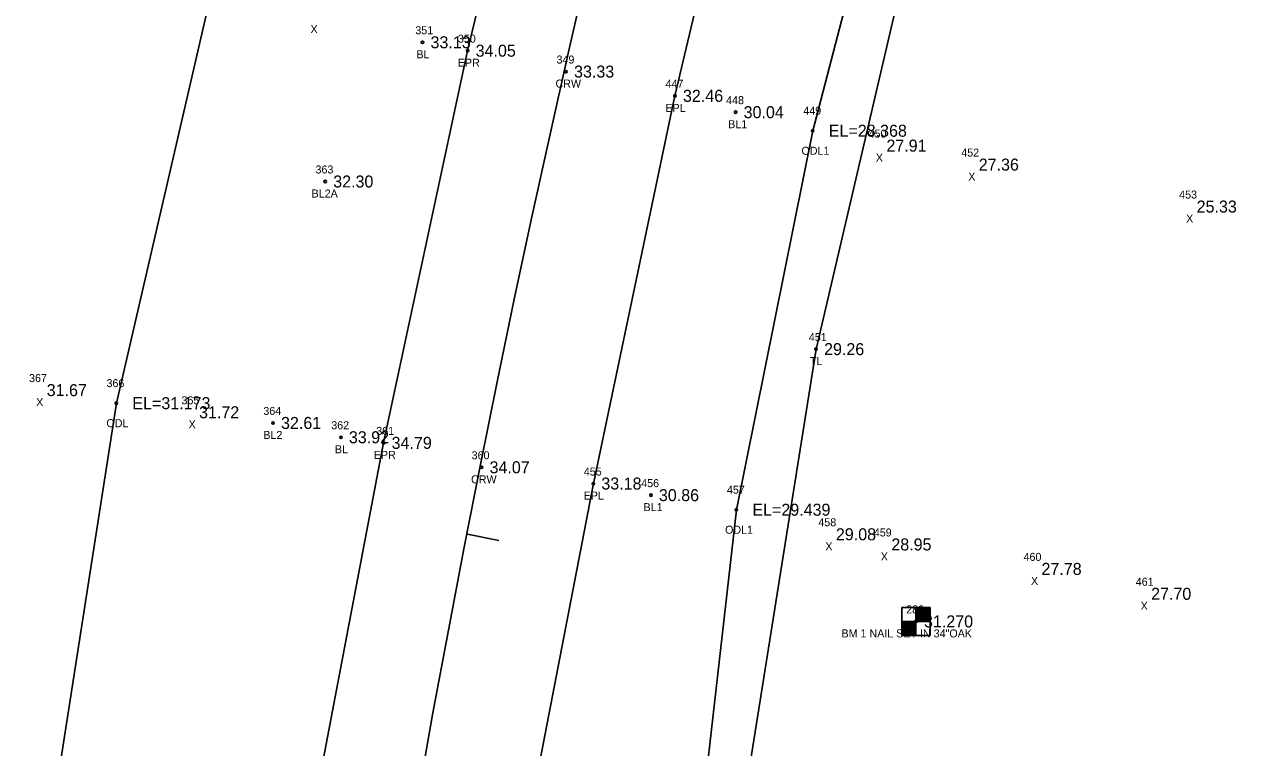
# Model space of a CAD drawing. Extents: x 2042117 to 2045853, y 303080 to 309569.
# Drawn here: x 2042820 to 2042971.5, y 307687.9 to 307778.3 of the extents above; entities that cross this region are included whole.
import ezdxf

# ---------------------------------------------------------------- set-up
doc = ezdxf.new("R2010")
doc.units = 0
for name, color, linetype in [('RD_DTM_BkLn_txCode', 7, 'Continuous'), ('RD_EX_H2O', 7, 'Continuous'), ('RD_EX_H2O_txCode', 7, 'Continuous'), ('RD_EX_Misc_txCode', 7, 'Continuous'), ('RD_EX_Road', 7, 'Continuous'), ('RD_EX_Road_txCode', 7, 'Continuous'), ('RD_EX_TX_H2O_ELEV', 7, 'Continuous'), ('RD_EX_TX_Misc_ELEV', 7, 'Continuous'), ('RD_EX_TX_Road_ELEV', 7, 'Continuous'), ('RD_EX_TX_VEG_ELEV', 7, 'Continuous'), ('RD_EX_VEG', 7, 'Continuous'), ('RD_EX_VEG_txCode', 7, 'Continuous'), ('RD_HC_Cl', 7, 'Continuous'), ('RD_HC_Data_Tic', 7, 'Continuous'), ('RD_HC_Survey', 7, 'Continuous'), ('RD_HC_Survey_ELEV', 7, 'Continuous'), ('RD_HC_Survey_txCode', 7, 'Continuous'), ('RD_SMD_Locator', 7, 'Continuous')]:
    doc.layers.add(name, color=color, linetype=linetype)

msp = doc.modelspace()

# ---------------------------------------------------------------- linework, layer by layer
at = {"layer": 'RD_EX_H2O'}
for points in [[(2043129.27, 308428.82), (2043103.11, 308386.53), (2043087.59, 308358.52), (2043078.21, 308342.14), (2043052.09, 308299.16), (2043025.98, 308255.36), (2043015.05, 308240.46), (2043007.57, 308236.11), (2042996.98, 308213.48), (2042981.31, 308163.04), (2042956.15, 308118.86), (2042936.41, 308071.81), (2042918.77, 308024.43), (2042903.29, 307975.96), (2042886.4, 307928.42), (2042872.04, 307879.53), (2042857.18, 307831.23), (2042843.33, 307782.22), (2042831.48, 307730.99), (2042823.97, 307682.68), (2042817.59, 307631.17), (2042809.6, 307580.86), (2042807.78, 307554.78)], [(2042954.71, 307908), (2042941.87, 307861.24), (2042931.11, 307813.3), (2042918.51, 307765.02), (2042908.96, 307717.68), (2042903.47, 307669.35), (2042893.06, 307622.27), (2042888.33, 307593.93)]]:
    msp.add_lwpolyline(points, dxfattribs=at)
at = {"layer": 'RD_EX_Road'}
for points in [[(2043150.45, 308415.87), (2043123.31, 308373.62), (2043097.1, 308331.18), (2043072.09, 308287.75), (2043048.26, 308243.82), (2043025.59, 308198.98), (2043003.92, 308153.61), (2042983.57, 308107.75), (2042964.45, 308061.45), (2042946.64, 308015.14), (2042930.05, 307967.71), (2042914.65, 307920.21), (2042900.21, 307872.25), (2042887.2, 307823.91), (2042875.38, 307775.02), (2042864.88, 307726.03), (2042855.57, 307677.22), (2042847.6, 307627.85), (2042840.73, 307578.32), (2042835.07, 307528.58), (2042830.98, 307478.6), (2042828.36, 307428.87), (2042826.99, 307378.91)], [(2043172.79, 308402.16), (2043145.1, 308359.37), (2043119.63, 308317.71), (2043094.79, 308274.94), (2043071.92, 308232.51), (2043049.11, 308188.03), (2043027.82, 308142.81), (2043007.75, 308097.66), (2042989.09, 308052.53), (2042971.66, 308006.7), (2042955.42, 307960.12), (2042939.67, 307912.41), (2042925.65, 307865.09), (2042912.69, 307817.39), (2042901.29, 307769.38), (2042891.09, 307720.95), (2042881.8, 307672.88), (2042874.23, 307624.44), (2042867.25, 307575.38), (2042861.55, 307525.78), (2042857.62, 307475.83), (2042855.03, 307427.78), (2042853.64, 307379.19)]]:
    msp.add_lwpolyline(points, dxfattribs=at)
at = {"layer": 'RD_EX_VEG'}
msp.add_lwpolyline([(2043048.7, 308112.2), (2043032.62, 308087.68), (2043027.55, 308080.82), (2043013.5, 308043.09), (2042994.71, 307997.39), (2042983.47, 307967.75), (2042952.97, 307870.73), (2042935.66, 307809.47), (2042918.92, 307737.74), (2042902.79, 307636.4), (2042902.54, 307635.29), (2042891, 307519.21), (2042885.61, 307482.85), (2042881.1, 307379.92)], dxfattribs=at)
at = {"layer": 'RD_HC_Cl'}
msp.add_arc((2044751.25, 307348.43), 1911.29, 137.68184, 219.86836, dxfattribs=at)
at = {"layer": 'RD_HC_Data_Tic'}
msp.add_line((2042875.36, 307714.62), (2042879.29, 307713.85), dxfattribs=at)
at = {"layer": 'RD_HC_Survey'}
for p, q in [((2042931.41, 307705.48), (2042931.41, 307701.98)), ((2042931.43, 307705.48), (2042931.43, 307703.73)), ((2042931.45, 307705.48), (2042931.45, 307703.73)), ((2042931.48, 307705.48), (2042931.48, 307703.73)), ((2042931.5, 307705.48), (2042931.5, 307703.73)), ((2042931.53, 307705.48), (2042931.53, 307703.73)), ((2042931.55, 307705.48), (2042931.55, 307703.73)), ((2042931.58, 307705.48), (2042931.58, 307703.73)), ((2042931.6, 307705.48), (2042931.6, 307703.73)), ((2042931.63, 307705.48), (2042931.63, 307703.73)), ((2042931.65, 307705.48), (2042931.65, 307703.73)), ((2042931.68, 307705.48), (2042931.68, 307703.73)), ((2042931.7, 307705.48), (2042931.7, 307703.73)), ((2042931.72, 307705.48), (2042931.72, 307703.73)), ((2042931.75, 307705.48), (2042931.75, 307703.73)), ((2042931.77, 307705.48), (2042931.77, 307703.73)), ((2042931.8, 307705.48), (2042931.8, 307703.73)), ((2042931.82, 307705.48), (2042931.82, 307703.73)), ((2042931.85, 307705.48), (2042931.85, 307703.73)), ((2042931.87, 307705.48), (2042931.87, 307703.73)), ((2042931.9, 307705.48), (2042931.9, 307703.73)), ((2042931.92, 307705.48), (2042931.92, 307703.73)), ((2042931.95, 307705.48), (2042931.95, 307703.73)), ((2042931.97, 307705.48), (2042931.97, 307703.73)), ((2042932, 307705.48), (2042932, 307703.73)), ((2042932.02, 307705.48), (2042932.02, 307703.73)), ((2042932.05, 307705.48), (2042932.05, 307703.73)), ((2042932.07, 307705.48), (2042932.07, 307703.73)), ((2042932.1, 307705.48), (2042932.1, 307703.73)), ((2042932.12, 307705.48), (2042932.12, 307703.73)), ((2042932.15, 307705.48), (2042932.15, 307703.73)), ((2042932.17, 307705.48), (2042932.17, 307703.73)), ((2042932.19, 307705.48), (2042932.19, 307703.73)), ((2042932.22, 307705.48), (2042932.22, 307703.73)), ((2042932.24, 307705.48), (2042932.24, 307703.73)), ((2042932.27, 307705.48), (2042932.27, 307703.73)), ((2042932.29, 307705.48), (2042932.29, 307703.73)), ((2042932.32, 307705.48), (2042932.32, 307703.73)), ((2042932.34, 307705.48), (2042932.34, 307703.73)), ((2042932.37, 307705.48), (2042932.37, 307703.73)), ((2042932.39, 307705.48), (2042932.39, 307703.73)), ((2042932.42, 307705.48), (2042932.42, 307703.73)), ((2042932.44, 307705.48), (2042932.44, 307703.73)), ((2042932.47, 307705.48), (2042932.47, 307703.73)), ((2042932.49, 307705.48), (2042932.49, 307703.73)), ((2042932.52, 307705.48), (2042932.52, 307703.73)), ((2042932.54, 307705.48), (2042932.54, 307703.73)), ((2042932.57, 307705.48), (2042932.57, 307703.73)), ((2042932.59, 307705.48), (2042932.59, 307703.73)), ((2042932.62, 307705.48), (2042932.62, 307703.73)), ((2042932.64, 307705.48), (2042932.64, 307703.73)), ((2042932.67, 307705.48), (2042932.67, 307703.73)), ((2042932.69, 307705.48), (2042932.69, 307703.73)), ((2042932.71, 307705.48), (2042932.71, 307703.73)), ((2042932.74, 307705.48), (2042932.74, 307703.73)), ((2042932.76, 307705.48), (2042932.76, 307703.73)), ((2042932.79, 307705.48), (2042932.79, 307703.73)), ((2042932.81, 307705.48), (2042932.81, 307703.73)), ((2042932.84, 307705.48), (2042932.84, 307703.73)), ((2042932.86, 307705.48), (2042932.86, 307703.73)), ((2042932.89, 307705.48), (2042932.89, 307703.73)), ((2042932.91, 307705.48), (2042932.91, 307703.73)), ((2042932.94, 307705.48), (2042932.94, 307703.73)), ((2042932.96, 307705.48), (2042932.96, 307703.73)), ((2042932.99, 307705.48), (2042932.99, 307703.73)), ((2042933.01, 307705.48), (2042933.01, 307703.73)), ((2042933.04, 307705.48), (2042933.04, 307703.73)), ((2042933.06, 307705.48), (2042933.06, 307703.73)), ((2042933.09, 307705.48), (2042933.09, 307703.73)), ((2042933.11, 307705.48), (2042933.11, 307703.73)), ((2042933.14, 307705.48), (2042933.14, 307703.73)), ((2042933.16, 307703.73), (2042929.66, 307703.73)), ((2042929.66, 307703.73), (2042929.66, 307701.98)), ((2042929.68, 307703.73), (2042929.68, 307701.98)), ((2042929.71, 307703.73), (2042929.71, 307701.98)), ((2042929.73, 307703.73), (2042929.73, 307701.98)), ((2042929.76, 307703.73), (2042929.76, 307701.98)), ((2042929.78, 307703.73), (2042929.78, 307701.98)), ((2042929.81, 307703.73), (2042929.81, 307701.98)), ((2042929.83, 307703.73), (2042929.83, 307701.98)), ((2042929.86, 307703.73), (2042929.86, 307701.98)), ((2042929.88, 307703.73), (2042929.88, 307701.98)), ((2042929.91, 307703.73), (2042929.91, 307701.98)), ((2042929.93, 307703.73), (2042929.93, 307701.98)), ((2042929.96, 307703.73), (2042929.96, 307701.98)), ((2042929.98, 307703.73), (2042929.98, 307701.98)), ((2042930.01, 307703.73), (2042930.01, 307701.98)), ((2042930.03, 307703.73), (2042930.03, 307701.98)), ((2042930.06, 307703.73), (2042930.06, 307701.98)), ((2042930.08, 307703.73), (2042930.08, 307701.98)), ((2042930.11, 307703.73), (2042930.11, 307701.98)), ((2042930.13, 307703.73), (2042930.13, 307701.98)), ((2042930.16, 307703.73), (2042930.16, 307701.98)), ((2042930.18, 307703.73), (2042930.18, 307701.98)), ((2042930.2, 307703.73), (2042930.2, 307701.98)), ((2042930.23, 307703.73), (2042930.23, 307701.98)), ((2042930.25, 307703.73), (2042930.25, 307701.98)), ((2042930.28, 307703.73), (2042930.28, 307701.98)), ((2042930.3, 307703.73), (2042930.3, 307701.98)), ((2042930.33, 307703.73), (2042930.33, 307701.98)), ((2042930.35, 307703.73), (2042930.35, 307701.98)), ((2042930.38, 307703.73), (2042930.38, 307701.98)), ((2042930.4, 307703.73), (2042930.4, 307701.98)), ((2042930.43, 307703.73), (2042930.43, 307701.98)), ((2042930.45, 307703.73), (2042930.45, 307701.98)), ((2042930.48, 307703.73), (2042930.48, 307701.98)), ((2042930.5, 307703.73), (2042930.5, 307701.98)), ((2042930.53, 307703.73), (2042930.53, 307701.98)), ((2042930.55, 307703.73), (2042930.55, 307701.98)), ((2042930.58, 307703.73), (2042930.58, 307701.98)), ((2042930.6, 307703.73), (2042930.6, 307701.98)), ((2042930.63, 307703.73), (2042930.63, 307701.98)), ((2042930.65, 307703.73), (2042930.65, 307701.98)), ((2042930.67, 307703.73), (2042930.67, 307701.98)), ((2042930.7, 307703.73), (2042930.7, 307701.98)), ((2042930.72, 307703.73), (2042930.72, 307701.98)), ((2042930.75, 307703.73), (2042930.75, 307701.98)), ((2042930.77, 307703.73), (2042930.77, 307701.98)), ((2042930.8, 307703.73), (2042930.8, 307701.98)), ((2042930.82, 307703.73), (2042930.82, 307701.98)), ((2042930.85, 307703.73), (2042930.85, 307701.98)), ((2042930.87, 307703.73), (2042930.87, 307701.98)), ((2042930.9, 307703.73), (2042930.9, 307701.98)), ((2042930.92, 307703.73), (2042930.92, 307701.98)), ((2042930.95, 307703.73), (2042930.95, 307701.98)), ((2042930.97, 307703.73), (2042930.97, 307701.98)), ((2042931, 307703.73), (2042931, 307701.98)), ((2042931.02, 307703.73), (2042931.02, 307701.98)), ((2042931.05, 307703.73), (2042931.05, 307701.98)), ((2042931.07, 307703.73), (2042931.07, 307701.98)), ((2042931.1, 307703.73), (2042931.1, 307701.98)), ((2042931.12, 307703.73), (2042931.12, 307701.98)), ((2042931.15, 307703.73), (2042931.15, 307701.98)), ((2042931.17, 307703.73), (2042931.17, 307701.98)), ((2042931.19, 307703.73), (2042931.19, 307701.98)), ((2042931.22, 307703.73), (2042931.22, 307701.98)), ((2042931.24, 307703.73), (2042931.24, 307701.98)), ((2042931.27, 307703.73), (2042931.27, 307701.98)), ((2042931.29, 307703.73), (2042931.29, 307701.98)), ((2042931.32, 307703.73), (2042931.32, 307701.98)), ((2042931.34, 307703.73), (2042931.34, 307701.98)), ((2042931.37, 307703.73), (2042931.37, 307701.98)), ((2042931.39, 307703.73), (2042931.39, 307701.98))]:
    msp.add_line(p, q, dxfattribs=at)
msp.add_lwpolyline([(2042933.16, 307705.48), (2042929.66, 307705.48), (2042929.66, 307701.98), (2042933.16, 307701.98)], close=True, dxfattribs=at)
at = {"layer": 'RD_SMD_Locator'}
for centre in [(2042869.74, 307776.07), (2042875.38, 307775.02), (2042887.68, 307772.41), (2042901.29, 307769.38), (2042908.87, 307767.34), (2042918.51, 307765.02), (2042857.58, 307758.68), (2042918.92, 307737.74), (2042831.48, 307730.99), (2042851.06, 307728.52), (2042859.54, 307726.73), (2042864.88, 307726.03), (2042877.12, 307722.98), (2042891.09, 307720.95), (2042898.28, 307719.5), (2042908.96, 307717.68), (2042931.41, 307703.73)]:
    msp.add_circle(centre, 0.15, dxfattribs=at)

# ---------------------------------------------------------------- texts
at = {"layer": 'RD_DTM_BkLn_txCode'}
for s, p in [('351', (2042868.84, 307777.07)), ('BL', (2042868.98, 307774.07)), ('448', (2042907.68, 307768.34)), ('BL1', (2042907.94, 307765.34)), ('363', (2042856.37, 307759.68)), ('BL2A', (2042855.88, 307756.68)), ('364', (2042849.85, 307729.52)), ('362', (2042858.34, 307727.73)), ('BL2', (2042849.85, 307726.52)), ('BL', (2042858.79, 307724.73)), ('456', (2042897.07, 307720.5)), ('BL1', (2042897.36, 307717.5))]:
    msp.add_text(s, height=1, dxfattribs=at).set_placement(p)
at = {"layer": 'RD_EX_H2O_txCode'}
for s, p in [('449', (2042917.33, 307767.02)), ('ODL1', (2042917.1, 307762.02)), ('366', (2042830.25, 307732.99)), ('ODL', (2042830.24, 307727.99)), ('457', (2042907.78, 307719.68)), ('ODL1', (2042907.55, 307714.68))]:
    msp.add_text(s, height=1, dxfattribs=at).set_placement(p)
at = {"layer": 'RD_EX_Misc_txCode'}
for s, p in [('X', (2042855.74, 307777.21)), ('450', (2042925.49, 307764.16)), ('X', (2042926.39, 307761.16)), ('452', (2042937.07, 307761.79)), ('X', (2042937.94, 307758.79)), ('453', (2042964.3, 307756.55)), ('X', (2042965.17, 307753.55)), ('367', (2042820.57, 307733.62)), ('X', (2042821.46, 307730.62)), ('365', (2042839.62, 307730.85)), ('X', (2042840.51, 307727.85)), ('458', (2042919.21, 307715.61)), ('459', (2042926.14, 307714.34)), ('X', (2042920.08, 307712.61)), ('X', (2042927.01, 307711.34)), ('460', (2042944.85, 307711.29)), ('X', (2042945.78, 307708.29)), ('461', (2042958.87, 307708.18)), ('X', (2042959.48, 307705.18))]:
    msp.add_text(s, height=1, dxfattribs=at).set_placement(p)
at = {"layer": 'RD_EX_Road_txCode'}
for s, p in [('350', (2042874.16, 307776.02)), ('EPR', (2042874.15, 307773.02)), ('447', (2042900.11, 307770.38)), ('EPL', (2042900.09, 307767.38)), ('361', (2042863.96, 307727.03)), ('EPR', (2042863.65, 307724.03)), ('455', (2042889.9, 307721.95)), ('EPL', (2042889.88, 307718.95))]:
    msp.add_text(s, height=1, dxfattribs=at).set_placement(p)
at = {"layer": 'RD_EX_TX_H2O_ELEV'}
for s, p in [('EL=28.368', (2042920.51, 307764.27)), ('EL=31.173', (2042833.48, 307730.24)), ('EL=29.439', (2042910.96, 307716.93))]:
    msp.add_text(s, height=1.5, dxfattribs=at).set_placement(p)
at = {"layer": 'RD_EX_TX_Misc_ELEV'}
for s, p in [('33.13', (2042870.74, 307775.32)), ('30.04', (2042909.87, 307766.59)), ('27.91', (2042927.71, 307762.41)), ('27.36', (2042939.25, 307760.04)), ('32.30', (2042858.58, 307757.93)), ('25.33', (2042966.48, 307754.8)), ('31.67', (2042822.78, 307731.87)), ('31.72', (2042841.82, 307729.1)), ('32.61', (2042852.06, 307727.77)), ('33.92', (2042860.54, 307725.98)), ('30.86', (2042899.28, 307718.75)), ('29.08', (2042921.4, 307713.86)), ('28.95', (2042928.33, 307712.59)), ('27.78', (2042947.09, 307709.54)), ('27.70', (2042960.79, 307706.43))]:
    msp.add_text(s, height=1.5, dxfattribs=at).set_placement(p)
at = {"layer": 'RD_EX_TX_Road_ELEV'}
for s, p in [('34.05', (2042876.38, 307774.27)), ('32.46', (2042902.29, 307768.63)), ('34.79', (2042865.88, 307725.28)), ('33.18', (2042892.09, 307720.2))]:
    msp.add_text(s, height=1.5, dxfattribs=at).set_placement(p)
at = {"layer": 'RD_EX_TX_VEG_ELEV'}
msp.add_text('29.26', height=1.5, dxfattribs=at).set_placement((2042919.92, 307736.99))
at = {"layer": 'RD_EX_VEG_txCode'}
for s, p in [('451', (2042918.02, 307738.74)), ('TL', (2042918.15, 307735.74))]:
    msp.add_text(s, height=1, dxfattribs=at).set_placement(p)
at = {"layer": 'RD_HC_Survey_ELEV'}
for s, p in [('33.33', (2042888.68, 307771.66)), ('34.07', (2042878.12, 307722.23)), ('31.270', (2042932.41, 307702.98))]:
    msp.add_text(s, height=1.5, dxfattribs=at).set_placement(p)
at = {"layer": 'RD_HC_Survey_txCode'}
for s, p in [('349', (2042886.49, 307773.41)), ('CRW', (2042886.36, 307770.41)), ('360', (2042875.88, 307723.98)), ('CRW', (2042875.81, 307720.98)), ('280', (2042930.19, 307704.73)), ('BM 1 NAIL SET IN 34"OAK', (2042922.1, 307701.73))]:
    msp.add_text(s, height=1, dxfattribs=at).set_placement(p)

doc.saveas('drawing.dxf')
